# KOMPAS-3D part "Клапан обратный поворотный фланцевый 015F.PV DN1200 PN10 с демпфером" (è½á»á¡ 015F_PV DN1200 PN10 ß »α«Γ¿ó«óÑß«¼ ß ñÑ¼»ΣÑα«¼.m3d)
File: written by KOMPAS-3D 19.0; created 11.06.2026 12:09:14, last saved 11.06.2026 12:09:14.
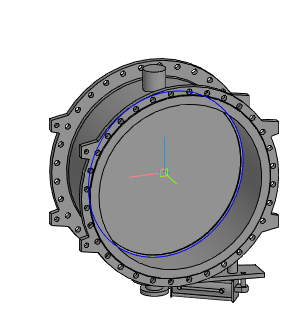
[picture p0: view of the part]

Document properties: Автор: Энергия; Полное имя файла: Z:\3.Личные\kachalov\001_3d для проектировщиков\5.5 Тип 015F.PV Клапан обратный поворотный с двумя эксцентриками\_stp_Клапан 015F.PV DN300-DN1200 с противовесом с демпфером\Клапан 015F_PV DN1200 PN10 с противовесом с демпфером.m3d

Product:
- Part/product: Клапан обратный поворотный фланцевый 015F.PV DN1200 PN10 с демпфером

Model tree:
1. Операция без истории:1
2. Сплайн:1
     Координата Y = 30; Координата Z = 600; Вес = 1; Координата X = 1200; Координата Y = 187.983; Координата Z = 600; Вес = 0.333333; Координата X = 1200; Координата Y = 187.983; Координата Z = -600; Вес = 0.333333; Координата Y = 30; Координата Z = -600; Вес = 1; Координата X = -1200; Координата Y = -127.983; Координата Z = -600; Вес = 0.333333; Координата X = -1200; Координата Y = -127.983; Координата Z = 600; Вес = 0.333333; Порядок = 4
